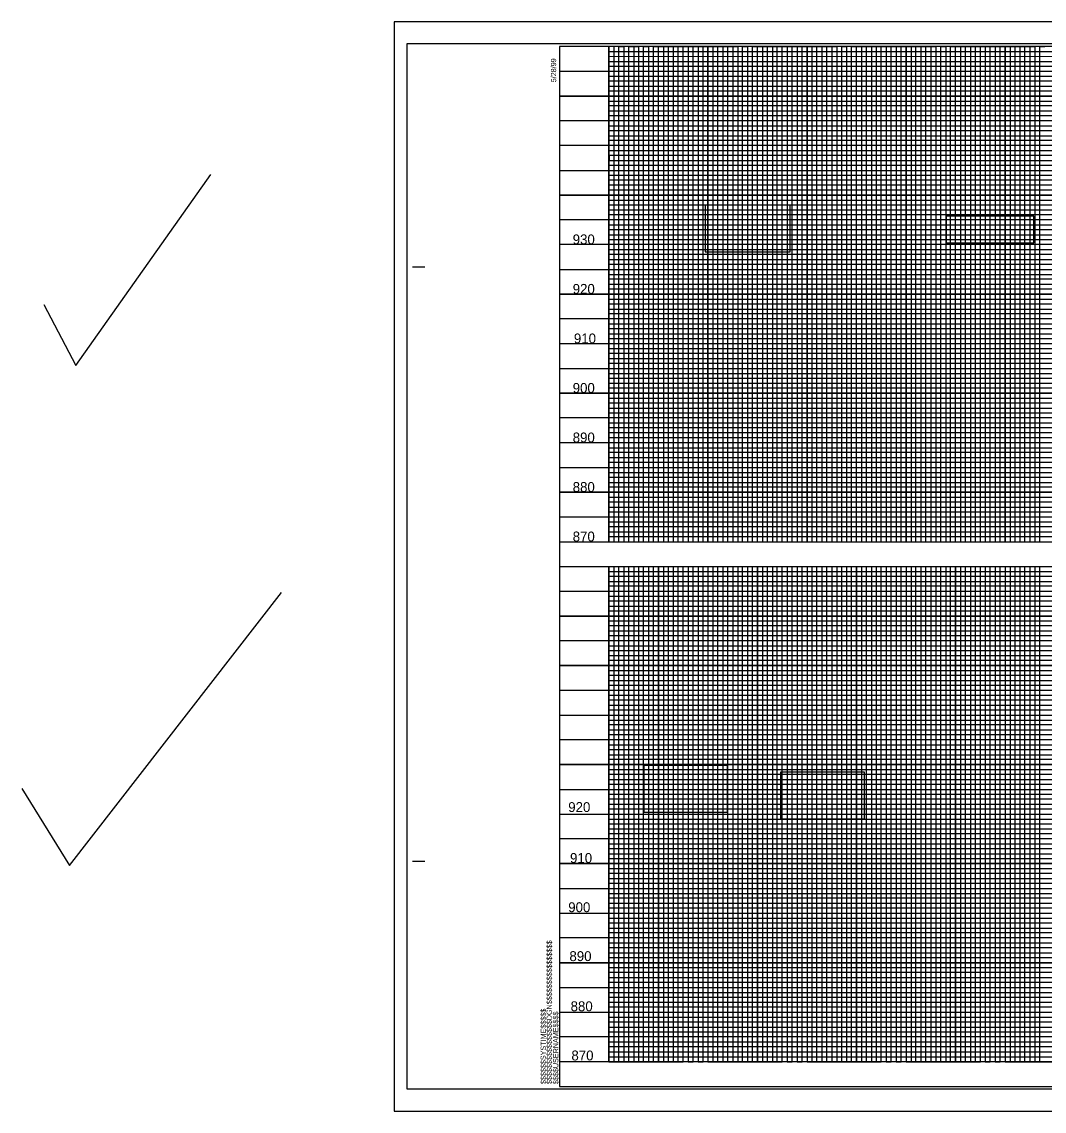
# Model space of a CAD drawing. Extents: x 1650661 to 1652901, y 832691 to 833791.
# Drawn here: x 1650661 to 1651694, y 832691 to 833791 of the extents above; entities that cross this region are included whole.
import ezdxf

# ---------------------------------------------------------------- set-up
doc = ezdxf.new("R2010")
doc.units = 0
for name, color, linetype in [('Exist Vertical Profile Vertical Axis Label', 7, 'Continuous'), ('Prop Grid Mask', 7, 'Continuous'), ('Sheet Cutting Line CELL', 7, 'Continuous'), ('Sheet DOT Grid CELL', 7, 'Continuous'), ('Sheet Layout Profile Border Port 2', 7, 'Continuous'), ('Sheet Plot Border Inside CELL', 7, 'Continuous'), ('Sheet Plot Border Outside CELL', 7, 'Continuous'), ('Sheet Profile CELL', 7, 'Continuous'), ('Sheet Profile Grid Major CELL', 7, 'Continuous'), ('Sheet Profile Grid Middle CELL', 7, 'Continuous'), ('Sheet Profile Grid Minor CELL', 7, 'Continuous'), ('Typical Text Centerline CELL', 7, 'Continuous')]:
    doc.layers.add(name, color=color, linetype=linetype)

msp = doc.modelspace()

# ---------------------------------------------------------------- linework, layer by layer
at = {"layer": 'Prop Grid Mask'}
for points in [[(1651351.5, 833605.9), (1651351.5, 833558.9), (1651437.1, 833558.9), (1651437.1, 833605.9)], [(1651594.6, 833594.8), (1651594.6, 833567.8), (1651683.2, 833567.8), (1651683.2, 833594.8)], [(1651289.4, 833040), (1651289.4, 832993), (1651373.9, 832993), (1651373.9, 833040)], [(1651427.4, 833033.2), (1651427.4, 832986.2), (1651512.2, 832986.2), (1651512.2, 833033.2)]]:
    msp.add_lwpolyline(points, close=True, dxfattribs=at)
at = {"layer": 'Sheet Cutting Line CELL'}
for p, q in [((1652721.3, 833791), (1651037.3, 833791)), ((1651037.3, 833791), (1651037.3, 832691)), ((1651037.3, 832691), (1652721.3, 832691))]:
    msp.add_line(p, q, dxfattribs=at)
at = {"layer": 'Sheet DOT Grid CELL'}
for p, q in [((1651254.3, 833266), (1651254.3, 833766)), ((1651304.3, 833266), (1651304.3, 833766)), ((1651354.3, 833266), (1651354.3, 833766)), ((1651404.3, 833266), (1651404.3, 833766)), ((1651454.3, 833266), (1651454.3, 833766)), ((1651504.3, 833266), (1651504.3, 833766)), ((1651554.3, 833266), (1651554.3, 833766)), ((1651604.3, 833266), (1651604.3, 833766)), ((1651654.3, 833266), (1651654.3, 833766)), ((1652504.2, 833716), (1651204.3, 833716)), ((1652504.2, 833666), (1651204.3, 833666)), ((1652504.3, 833616), (1651204.3, 833616)), ((1652704.3, 833566), (1651204.3, 833566)), ((1652704.3, 833516), (1651204.3, 833516)), ((1652704.3, 833466), (1651204.3, 833466)), ((1652704.3, 833416), (1651204.3, 833416)), ((1652704.3, 833366), (1651204.3, 833366)), ((1652704.3, 833316), (1651204.3, 833316)), ((1651204.3, 833241), (1652704.2, 833241)), ((1651254.3, 833241), (1651254.3, 832741)), ((1651304.3, 833241), (1651304.3, 832741)), ((1651354.3, 833241), (1651354.3, 832741)), ((1651404.3, 833241), (1651404.3, 832741)), ((1651454.3, 833241), (1651454.3, 832741)), ((1651504.3, 833241), (1651504.3, 832741)), ((1651554.3, 833241), (1651554.3, 832741)), ((1651604.3, 833241), (1651604.3, 832741)), ((1651654.3, 833241), (1651654.3, 832741)), ((1651204.3, 833191), (1652704.2, 833191)), ((1651204.3, 833141), (1652704.2, 833141)), ((1651204.3, 833091), (1652704.2, 833091)), ((1651204.3, 833041), (1652704.2, 833041)), ((1651204.3, 832991), (1652704.2, 832991)), ((1651204.3, 832941), (1652704.2, 832941)), ((1651204.3, 832891), (1652704.2, 832891)), ((1651204.3, 832841), (1652704.2, 832841)), ((1651204.3, 832791), (1652704.2, 832791))]:
    msp.add_line(p, q, dxfattribs=at)
at = {"layer": 'Sheet Layout Profile Border Port 2'}
msp.add_lwpolyline([(1651254.3, 833241), (1652654.3, 833241), (1652654.3, 832741), (1651254.3, 832741)], close=True, dxfattribs=at)
at = {"layer": 'Sheet Plot Border Inside CELL'}
msp.add_lwpolyline([(1651050.3, 832713.5), (1652716.8, 832713.5), (1652716.8, 833768.6), (1651050.3, 833768.6)], close=True, dxfattribs=at)
at = {"layer": 'Sheet Plot Border Outside CELL'}
for p, q in [((1650709.7, 832939), (1650923.8, 833214.8)), ((1650661.5, 833016.7), (1650709.7, 832939))]:
    msp.add_line(p, q, dxfattribs=at)
msp.add_lwpolyline([(1651037.3, 832691), (1652721.3, 832691), (1652721.3, 833791), (1651037.3, 833791)], close=True, dxfattribs=at)
at = {"layer": 'Sheet Profile CELL'}
for p, q in [((1651055.8, 833543.5), (1651068.3, 833543.5)), ((1651204.3, 833266), (1652704.3, 833266)), ((1651204.3, 833241), (1652704.3, 833241)), ((1651055.8, 832943.5), (1651068.3, 832943.5)), ((1652704.3, 832741), (1651204.3, 832741)), ((1651204.3, 832716), (1652704.3, 832716)), ((1651204.3, 832716), (1651204.3, 832716)), ((1651204.3, 832716), (1651204.3, 832716)), ((1651204.3, 832716), (1651204.3, 832716)), ((1651204.3, 832716), (1651204.3, 832716)), ((1651204.3, 832716), (1651204.3, 832716)), ((1651204.3, 832716), (1651204.3, 832716)), ((1651204.3, 832716), (1651204.3, 832716))]:
    msp.add_line(p, q, dxfattribs=at)
msp.add_lwpolyline([(1652704.3, 833766), (1651204.3, 833766), (1651204.3, 832716), (1652704.3, 832716)], close=True, dxfattribs=at)
msp.add_lwpolyline([(1651241.8, 832716), (1651241.8, 832716)], dxfattribs=at)
at = {"layer": 'Sheet Profile Grid Major CELL'}
msp.add_line((1651204.3, 832741), (1651204.3, 832741), dxfattribs=at)
for points in [[(1651254.3, 833766), (1651254.3, 833266), (1651304.3, 833266), (1651304.3, 833766), (1651354.3, 833766), (1651354.3, 833266), (1651404.3, 833266), (1651404.3, 833766), (1651454.3, 833766), (1651454.3, 833266), (1651504.3, 833266), (1651504.3, 833766), (1651554.3, 833766), (1651554.3, 833266), (1651604.3, 833266), (1651604.3, 833766), (1651654.3, 833766), (1651654.3, 833266), (1651704.3, 833266)], [(1651204.3, 833716), (1652504.3, 833716)], [(1652504.3, 833666), (1651204.3, 833666), (1651204.3, 833616), (1652504.3, 833616)], [(1652704.3, 833566), (1651204.3, 833566), (1651204.3, 833516), (1652704.3, 833516)], [(1652704.3, 833466), (1651204.3, 833466), (1651204.3, 833416), (1652704.3, 833416)], [(1652704.3, 833366), (1651204.3, 833366), (1651204.3, 833366), (1651204.3, 833316), (1652704.3, 833316)], [(1651254.3, 833241), (1651254.3, 832741), (1651304.3, 832741), (1651304.3, 833241), (1651354.3, 833241), (1651354.3, 832741), (1651404.3, 832741), (1651404.3, 833241), (1651454.3, 833241), (1651454.3, 832741), (1651504.3, 832741), (1651504.3, 833241), (1651554.3, 833241), (1651554.3, 832741), (1651604.3, 832741), (1651604.3, 833241), (1651654.3, 833241), (1651654.3, 832741), (1651704.3, 832741)], [(1652704.3, 833191), (1651204.3, 833191)], [(1652704.3, 833141), (1651204.3, 833141), (1651204.3, 833091), (1652704.3, 833091)], [(1652704.3, 833041), (1651204.3, 833041), (1651204.3, 832991), (1652704.3, 832991)], [(1652704.3, 832941), (1651204.3, 832941), (1651204.3, 832891), (1652704.3, 832891)], [(1652704.3, 832841), (1651204.3, 832841), (1651204.3, 832841), (1651204.3, 832791), (1652704.3, 832791)], [(1652704.3, 832741), (1651204.3, 832741)]]:
    msp.add_lwpolyline(points, dxfattribs=at)
at = {"layer": 'Sheet Profile Grid Middle CELL'}
msp.add_line((1651204.3, 833741), (1652354.3, 833741), dxfattribs=at)
for points in [[(1651279.3, 833766), (1651279.3, 833266), (1651329.3, 833266), (1651329.3, 833766), (1651379.3, 833766), (1651379.3, 833266), (1651429.3, 833266), (1651429.3, 833766), (1651479.3, 833766), (1651479.3, 833266), (1651529.3, 833266), (1651529.3, 833766), (1651579.3, 833766), (1651579.3, 833266), (1651629.3, 833266), (1651629.3, 833766), (1651679.3, 833766), (1651679.3, 833266), (1651729.3, 833266)], [(1652504.3, 833691), (1651204.3, 833691), (1651204.3, 833641), (1652504.3, 833641)], [(1652704.3, 833591), (1651204.3, 833591), (1651204.3, 833541), (1652529.3, 833541)], [(1652704.3, 833491), (1651204.3, 833491), (1651204.3, 833441), (1652704.3, 833441)], [(1652704.3, 833391), (1651204.3, 833391), (1651204.3, 833341), (1652704.3, 833341)], [(1652704.3, 833291), (1651204.3, 833291)], [(1651229.3, 833241), (1651279.3, 833241), (1651279.3, 832741), (1651329.3, 832741), (1651329.3, 833241), (1651379.3, 833241), (1651379.3, 832741), (1651429.3, 832741), (1651429.3, 833241), (1651479.3, 833241), (1651479.3, 832741), (1651529.3, 832741), (1651529.3, 833241), (1651579.3, 833241), (1651579.3, 832741), (1651629.3, 832741), (1651629.3, 833241), (1651679.3, 833241), (1651679.3, 832741), (1651729.3, 832741)], [(1651204.3, 833216), (1652704.3, 833216)], [(1652704.3, 833166), (1651204.3, 833166), (1651204.3, 833116), (1652704.3, 833116)], [(1652704.3, 833066), (1651204.3, 833066), (1651204.3, 833016), (1652704.3, 833016)], [(1652704.3, 832966), (1651204.3, 832966), (1651204.3, 832916), (1652704.3, 832916)], [(1652704.3, 832866), (1651204.3, 832866), (1651204.3, 832816), (1652704.3, 832816)], [(1652704.3, 832766), (1651204.3, 832766)]]:
    msp.add_lwpolyline(points, dxfattribs=at)
at = {"layer": 'Sheet Profile Grid Minor CELL'}
for p, q in [((1651254.3, 833761), (1652354.3, 833761)), ((1651254.3, 833756), (1651254.3, 833756)), ((1651254.3, 833756), (1651254.3, 833756)), ((1651254.3, 833756), (1651254.3, 833756)), ((1652354.3, 833756), (1651254.3, 833755.7)), ((1651254.3, 833751), (1652354.3, 833751)), ((1652504.2, 833631), (1651254.3, 833631)), ((1652504.3, 833626), (1651254.3, 833626)), ((1652504.3, 833621), (1651254.3, 833621)), ((1651254.3, 833611), (1652504.3, 833611)), ((1652504.3, 833606), (1651254.3, 833606)), ((1651254.3, 833601), (1652654.3, 833601)), ((1652654.3, 833581), (1651254.3, 833581)), ((1651254.3, 833576), (1652654.3, 833576)), ((1652654.3, 833556), (1651254.3, 833556)), ((1651254.3, 833551), (1652654.3, 833551)), ((1652654.3, 833531), (1651254.3, 833531)), ((1651254.3, 833526), (1652654.3, 833526)), ((1652654.3, 833521), (1651254.3, 833521)), ((1651254.3, 833511), (1652654.3, 833511)), ((1652654.3, 833506), (1651254.3, 833506)), ((1651254.3, 833501), (1652654.3, 833501)), ((1652654.3, 833496), (1651254.3, 833496)), ((1651254.3, 833486), (1652654.3, 833486)), ((1652654.3, 833481), (1651254.3, 833481)), ((1651254.3, 833476), (1652654.3, 833476)), ((1652654.3, 833471), (1651254.3, 833471)), ((1651254.3, 833461), (1652654.3, 833461)), ((1652654.3, 833456), (1651254.3, 833456)), ((1651254.3, 833451), (1652654.3, 833451)), ((1652654.3, 833446), (1651254.3, 833446)), ((1651254.3, 833436), (1652654.3, 833436)), ((1652654.3, 833431), (1651254.3, 833431)), ((1651254.3, 833426), (1652654.3, 833426)), ((1652654.3, 833421), (1651254.3, 833421)), ((1651254.3, 833411), (1652654.3, 833411)), ((1652654.3, 833406), (1651254.3, 833406)), ((1651254.3, 833401), (1652654.3, 833401)), ((1652654.3, 833396), (1651254.3, 833396)), ((1651254.3, 833386), (1652654.3, 833386)), ((1652654.3, 833381), (1651254.3, 833381)), ((1652654.3, 833376), (1651254.3, 833376)), ((1652654.3, 833371), (1651254.3, 833371)), ((1651254.3, 833361), (1652654.3, 833361)), ((1652654.3, 833356), (1651254.3, 833356)), ((1651254.3, 833351), (1652654.3, 833351)), ((1652654.3, 833346), (1651254.3, 833346)), ((1651254.3, 833336), (1652654.3, 833336)), ((1652654.3, 833331), (1651254.3, 833331)), ((1651254.3, 833326), (1652654.3, 833326)), ((1652654.3, 833321), (1651254.3, 833321)), ((1651254.3, 833311), (1652654.3, 833311)), ((1652654.3, 833306), (1651254.3, 833306)), ((1651254.3, 833301), (1652654.3, 833301)), ((1652654.3, 833296), (1651254.3, 833296)), ((1651254.3, 833286), (1652654.3, 833286)), ((1652654.3, 833281), (1651254.3, 833281)), ((1651254.3, 833276), (1652654.3, 833276)), ((1651254.3, 833236), (1652654.3, 833236)), ((1652654.3, 833231), (1651254.3, 833231)), ((1651254.3, 833226), (1652654.3, 833226)), ((1652654.3, 833221), (1651254.3, 833221)), ((1651254.3, 833211), (1652654.3, 833211)), ((1652654.3, 833206), (1651254.3, 833206)), ((1651254.3, 833201), (1652654.3, 833201)), ((1652654.3, 833196), (1651254.3, 833196)), ((1651254.3, 833186), (1652654.3, 833186)), ((1652654.3, 833181), (1651254.3, 833181)), ((1651254.3, 833176), (1652654.3, 833176)), ((1652654.3, 833171), (1651254.3, 833171)), ((1651254.3, 833161), (1652654.3, 833161)), ((1652654.3, 833156), (1651254.3, 833156)), ((1651254.3, 833151), (1652654.3, 833151)), ((1652654.3, 833146), (1651254.3, 833146)), ((1651254.3, 833136), (1652654.3, 833136)), ((1652654.3, 833131), (1651254.3, 833131)), ((1651254.3, 833126), (1652654.3, 833126)), ((1652654.3, 833121), (1651254.3, 833121)), ((1651254.3, 833111), (1652654.3, 833111)), ((1652654.3, 833106), (1651254.3, 833106)), ((1651254.3, 833101), (1652654.3, 833101)), ((1652654.3, 833096), (1651254.3, 833096)), ((1651254.3, 833086), (1652654.3, 833086)), ((1652654.3, 833081), (1651254.3, 833081)), ((1651254.3, 833076), (1652654.3, 833076)), ((1652654.3, 833071), (1651254.3, 833071)), ((1651254.3, 833061), (1652654.3, 833061)), ((1652654.3, 833056), (1651254.3, 833056)), ((1651254.3, 833051), (1652654.3, 833051)), ((1652654.3, 833046), (1651254.3, 833046.2)), ((1651254.3, 833036), (1652654.3, 833036)), ((1652654.3, 833031), (1651254.3, 833031)), ((1651254.3, 833026), (1652654.3, 833026)), ((1652654.3, 833021), (1651254.3, 833021)), ((1651254.3, 833011), (1652654.3, 833011)), ((1652654.3, 833006), (1651254.3, 833006)), ((1651254.3, 833001), (1652654.3, 833001)), ((1652654.3, 832996), (1651254.3, 832996)), ((1651254.3, 832986), (1652654.3, 832986)), ((1652654.3, 832981), (1651254.3, 832981)), ((1651254.3, 832976), (1652654.3, 832976)), ((1652654.3, 832971), (1651254.3, 832971)), ((1651254.3, 832961), (1652654.3, 832961)), ((1652654.3, 832956), (1651254.3, 832956)), ((1651254.3, 832951), (1652654.3, 832951)), ((1652654.3, 832946), (1651254.3, 832946)), ((1651254.3, 832936), (1652654.3, 832936)), ((1652654.3, 832931), (1651254.3, 832931)), ((1651254.3, 832926), (1652654.3, 832926)), ((1652654.3, 832921), (1651254.3, 832921)), ((1651254.3, 832911), (1652654.3, 832911)), ((1652654.3, 832906), (1651254.3, 832906)), ((1651254.3, 832901), (1652654.3, 832901)), ((1652654.3, 832896), (1651254.3, 832896)), ((1651254.3, 832886), (1652654.3, 832886)), ((1652654.3, 832881), (1651254.3, 832881)), ((1651254.3, 832876), (1652654.3, 832876)), ((1652654.3, 832871), (1651254.3, 832871)), ((1651254.3, 832861), (1652654.3, 832861)), ((1652654.3, 832856), (1651254.3, 832856)), ((1651254.3, 832851), (1652654.3, 832851)), ((1652654.3, 832846), (1651254.3, 832846)), ((1651254.3, 832836), (1652654.3, 832836)), ((1652654.3, 832831), (1651254.3, 832831)), ((1651254.3, 832826), (1652654.3, 832826)), ((1652654.3, 832821), (1651254.3, 832821)), ((1651254.3, 832811), (1652654.3, 832811)), ((1652654.3, 832806), (1651254.3, 832806)), ((1651254.3, 832801), (1652654.3, 832801)), ((1652654.3, 832796), (1651254.3, 832796)), ((1651254.3, 832786), (1652654.3, 832786)), ((1652654.3, 832781), (1651254.3, 832781)), ((1651254.3, 832776), (1652654.3, 832776)), ((1652654.3, 832771), (1651254.3, 832771)), ((1651254.3, 832761), (1652654.3, 832761)), ((1652654.3, 832756), (1651254.3, 832756)), ((1651254.3, 832751), (1652654.3, 832751)), ((1651254.3, 832746), (1652654.3, 832746))]:
    msp.add_line(p, q, dxfattribs=at)
for points in [[(1651259.3, 833766), (1651259.3, 833266), (1651264.3, 833266), (1651264.3, 833766), (1651269.3, 833766), (1651269.3, 833266), (1651274.3, 833266), (1651274.3, 833766), (1651284.3, 833766), (1651284.3, 833266), (1651289.3, 833266), (1651289.3, 833766), (1651294.3, 833766), (1651294.3, 833266), (1651299.3, 833266), (1651309.3, 833266), (1651314.3, 833266), (1651314.3, 833766), (1651319.3, 833766), (1651319.3, 833266), (1651324.3, 833266), (1651324.3, 833766), (1651334.3, 833766), (1651334.3, 833266), (1651339.3, 833266), (1651339.3, 833766), (1651344.3, 833766), (1651344.3, 833266), (1651349.3, 833266), (1651349.3, 833766), (1651359.3, 833766), (1651359.3, 833266), (1651364.3, 833266), (1651364.3, 833766), (1651369.3, 833766), (1651369.3, 833266), (1651374.3, 833266), (1651374.3, 833766), (1651384.3, 833766), (1651384.3, 833266), (1651389.3, 833266), (1651389.3, 833766), (1651394.3, 833766), (1651394.3, 833266), (1651399.3, 833266), (1651399.3, 833766), (1651409.3, 833766), (1651409.3, 833266), (1651414.3, 833266), (1651414.3, 833766), (1651419.3, 833766), (1651419.3, 833266), (1651424.3, 833266), (1651424.3, 833766), (1651434.3, 833766), (1651434.3, 833266), (1651439.3, 833266), (1651439.3, 833766), (1651444.3, 833766), (1651444.3, 833266), (1651449.3, 833266), (1651449.3, 833766), (1651459.3, 833766), (1651459.3, 833266), (1651464.3, 833266), (1651464.3, 833766), (1651469.3, 833766), (1651469.3, 833266)], [(1651299.3, 833266), (1651299.3, 833766), (1651309.3, 833766), (1651309.3, 833266)], [(1651469.3, 833266), (1651474.3, 833266), (1651474.3, 833766), (1651484.3, 833766), (1651484.3, 833266), (1651489.3, 833266), (1651489.3, 833766), (1651494.3, 833766), (1651494.3, 833266), (1651499.3, 833266), (1651499.3, 833766), (1651509.3, 833766), (1651509.3, 833266), (1651514.3, 833266), (1651514.3, 833766), (1651519.3, 833766), (1651519.3, 833266), (1651524.3, 833266), (1651524.3, 833766), (1651534.3, 833766), (1651534.3, 833266), (1651539.3, 833266), (1651539.3, 833766), (1651544.3, 833766), (1651544.3, 833266), (1651549.3, 833266), (1651549.3, 833766), (1651559.3, 833766), (1651559.3, 833266), (1651564.3, 833266), (1651564.3, 833766), (1651569.3, 833766), (1651569.3, 833266), (1651574.3, 833266), (1651574.3, 833766), (1651584.3, 833766), (1651584.3, 833266), (1651589.3, 833266), (1651589.3, 833766), (1651594.3, 833766), (1651594.3, 833266), (1651599.3, 833266), (1651599.3, 833766), (1651609.3, 833766), (1651609.3, 833266), (1651614.3, 833266), (1651614.3, 833766), (1651619.3, 833766), (1651619.3, 833266), (1651624.3, 833266), (1651624.3, 833766), (1651634.3, 833766), (1651634.3, 833266), (1651639.3, 833266), (1651639.3, 833766), (1651644.3, 833766), (1651644.3, 833266), (1651649.3, 833266), (1651649.3, 833766), (1651659.3, 833766), (1651659.3, 833266), (1651664.3, 833266), (1651664.3, 833766), (1651669.3, 833766), (1651669.3, 833266), (1651674.3, 833266), (1651674.3, 833766), (1651684.3, 833766), (1651684.3, 833266), (1651689.3, 833266), (1651689.3, 833766), (1651694.3, 833766)], [(1652354.3, 833746), (1651254.3, 833746), (1651254.3, 833736), (1652504.3, 833736)], [(1652504.2, 833731), (1651254.3, 833731), (1651254.3, 833726), (1652504.3, 833726)], [(1652504.3, 833721), (1651254.3, 833721), (1651254.3, 833711), (1652504.3, 833711)], [(1652504.3, 833706), (1651254.3, 833706), (1651254.3, 833701), (1652504.3, 833701)], [(1652504.3, 833696), (1651254.3, 833696), (1651254.3, 833686), (1652504.3, 833686)], [(1652504.3, 833681), (1651254.3, 833681), (1651254.3, 833676), (1652504.3, 833676)], [(1652504.3, 833671), (1651254.3, 833671), (1651254.3, 833661), (1652504.3, 833661)], [(1652504.3, 833646), (1651254.3, 833646), (1651254.3, 833636), (1652504.3, 833636)], [(1652504.3, 833655.9), (1651254.4, 833655.9), (1651254.4, 833651), (1652504.3, 833651)], [(1652654.3, 833596), (1651254.3, 833596), (1651254.3, 833586), (1652654.3, 833586)], [(1652654.3, 833571), (1651254.3, 833571), (1651254.3, 833561), (1652654.3, 833561)], [(1652654.3, 833546), (1651254.3, 833546), (1651254.3, 833536), (1652654.3, 833536)], [(1652654.3, 833271), (1651254.3, 833271)], [(1651254.3, 833241), (1651259.3, 833241), (1651259.3, 832741), (1651264.3, 832741), (1651264.3, 833241), (1651269.3, 833241), (1651269.3, 832741), (1651274.3, 832741), (1651274.3, 833241), (1651284.3, 833241), (1651284.3, 832741), (1651289.3, 832741), (1651289.3, 833241), (1651294.3, 833241), (1651294.3, 832741), (1651299.3, 832741), (1651309.3, 832741), (1651314.3, 832741), (1651314.3, 833241), (1651319.3, 833241), (1651319.3, 832741), (1651324.3, 832741), (1651324.3, 833241), (1651334.3, 833241), (1651334.3, 832741), (1651339.3, 832741), (1651339.3, 833241), (1651344.3, 833241), (1651344.3, 832741), (1651349.3, 832741), (1651349.3, 833241), (1651359.3, 833241), (1651359.3, 832741), (1651364.3, 832741), (1651364.3, 833241), (1651369.3, 833241), (1651369.3, 832741), (1651374.3, 832741), (1651374.3, 833241), (1651384.3, 833241), (1651384.3, 832741), (1651389.3, 832741), (1651389.3, 833241), (1651394.3, 833241), (1651394.3, 832741), (1651399.3, 832741), (1651399.3, 833241), (1651409.3, 833241), (1651409.3, 832741), (1651414.3, 832741), (1651414.3, 833241), (1651419.3, 833241), (1651419.3, 832741), (1651424.3, 832741), (1651424.3, 833241), (1651434.3, 833241), (1651434.3, 832741), (1651439.3, 832741), (1651439.3, 833241), (1651444.3, 833241), (1651444.3, 832741), (1651449.3, 832741), (1651449.3, 833241), (1651459.3, 833241), (1651459.3, 832741), (1651464.3, 832741), (1651464.3, 833241), (1651469.3, 833241), (1651469.3, 832741)], [(1651299.3, 832741), (1651299.3, 833241), (1651309.3, 833241), (1651309.3, 832741)], [(1651469.3, 832741), (1651474.3, 832741), (1651474.3, 833241), (1651484.3, 833241), (1651484.3, 832741), (1651489.3, 832741), (1651489.3, 833241), (1651494.3, 833241), (1651494.3, 832741), (1651499.3, 832741), (1651499.3, 833241), (1651509.3, 833241), (1651509.3, 832741), (1651514.3, 832741), (1651514.3, 833241), (1651519.3, 833241), (1651519.3, 832741), (1651524.3, 832741), (1651524.3, 833241), (1651534.3, 833241), (1651534.3, 832741), (1651539.3, 832741), (1651539.3, 833241), (1651544.3, 833241), (1651544.3, 832741), (1651549.3, 832741), (1651549.3, 833241), (1651559.3, 833241), (1651559.3, 832741), (1651564.3, 832741), (1651564.3, 833241), (1651569.3, 833241), (1651569.3, 832741), (1651574.3, 832741), (1651574.3, 833241), (1651584.3, 833241), (1651584.3, 832741), (1651589.3, 832741), (1651589.3, 833241), (1651594.3, 833241), (1651594.3, 832741), (1651599.3, 832741), (1651599.3, 833241), (1651609.3, 833241), (1651609.3, 832741), (1651614.3, 832741), (1651614.3, 833241), (1651619.3, 833241), (1651619.3, 832741), (1651624.3, 832741), (1651624.3, 833241), (1651634.3, 833241), (1651634.3, 832741), (1651639.3, 832741), (1651639.3, 833241), (1651644.3, 833241), (1651644.3, 832741), (1651649.3, 832741), (1651649.3, 833241), (1651659.3, 833241), (1651659.3, 832741), (1651664.3, 832741), (1651664.3, 833241), (1651669.3, 833241), (1651669.3, 832741), (1651674.3, 832741), (1651674.3, 833241), (1651684.3, 833241), (1651684.3, 832741), (1651689.3, 832741), (1651689.3, 833241), (1651694.3, 833241)]]:
    msp.add_lwpolyline(points, dxfattribs=at)
at = {"layer": 'Typical Text Centerline CELL'}
for p, q in [((1650716, 833444), (1650852.5, 833636.8)), ((1650683.8, 833505.6), (1650716, 833444))]:
    msp.add_line(p, q, dxfattribs=at)

# ---------------------------------------------------------------- texts
at = {"layer": 'Exist Vertical Profile Vertical Axis Label'}
for s, p in [('930', (1651217.7, 833566.3)), ('920', (1651217.7, 833516.3)), ('910', (1651218.9, 833466.3)), ('900', (1651217.7, 833416.3)), ('890', (1651217.7, 833366.3)), ('880', (1651217.7, 833316.3)), ('870', (1651217.7, 833266.3)), ('920', (1651213.2, 832993.1)), ('910', (1651215, 832941.7)), ('900', (1651213.2, 832892)), ('890', (1651214.4, 832842.6)), ('880', (1651215.6, 832792)), ('870', (1651216.4, 832742.3))]:
    msp.add_text(s, height=10, dxfattribs=at).set_placement(p)
at = {"layer": 'Sheet Profile CELL'}
for s, p in [('5/28/99', (1651201, 833729.9)), ('$$$$$$$$$$$$$$$$DGN$$$$$$$$$$$$$$$$', (1651196.6, 832718.4)), ('$$$$$$SYSTIME$$$$$', (1651190.6, 832718.4)), ('$$$$USERNAME$$$$', (1651203.2, 832718.4))]:
    msp.add_text(s, height=5.25, rotation=90, dxfattribs=at).set_placement(p)

doc.saveas('drawing.dxf')
